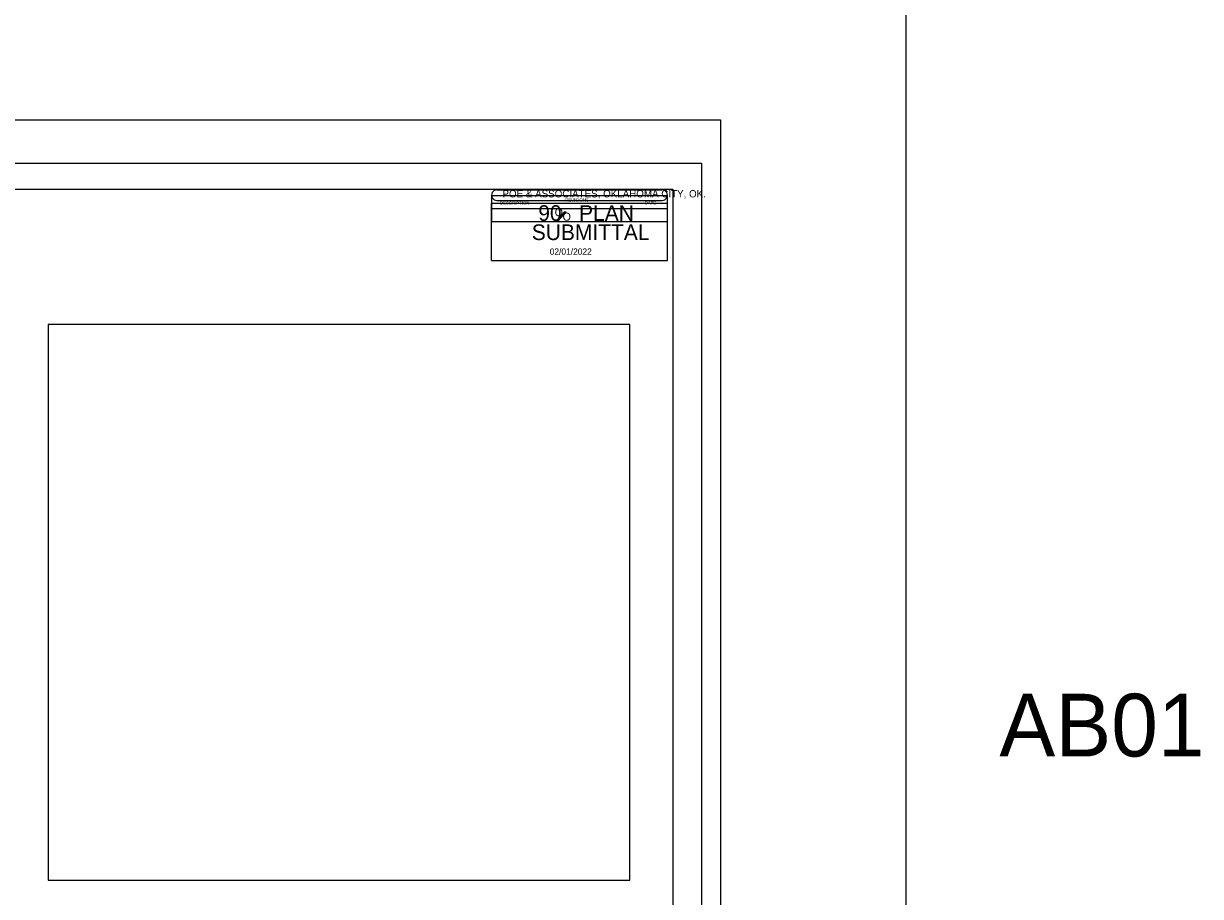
# Model space of a CAD drawing. Extents: x 12306 to 12361.5, y 578.9 to 640.4.
# Drawn here: x 12339.03 to 12361.54, y 593.62 to 610.31 of the extents above; entities that cross this region are included whole.
import ezdxf

# ---------------------------------------------------------------- set-up
doc = ezdxf.new("R2010")
doc.units = 0
for name, color, linetype in [('S', 7, 'Continuous'), ('SHT_Plot_Shape_Full', 7, 'Continuous'), ('SHT_Plot_Shape_Half', 7, 'Continuous'), ('SHT_Sheet_Border', 7, 'Continuous'), ('SHT_Stamp_90_Submit', 7, 'Continuous'), ('SHT_Stamp_Rev_Block', 7, 'Continuous'), ('T', 7, 'Continuous')]:
    doc.layers.add(name, color=color, linetype=linetype)

msp = doc.modelspace()

# ---------------------------------------------------------------- linework, layer by layer
at = {"layer": 'Defpoints'}
msp.add_lwpolyline([(12339.503, 593.929), (12350.628, 593.929), (12350.628, 604.554), (12339.503, 604.554)], close=True, dxfattribs=at)
at = {"layer": 'S'}
msp.add_lwpolyline([(12355.912, 640.357), (12312.476, 640.357), (12312.476, 578.901), (12355.912, 578.901)], close=True, dxfattribs=at)
at = {"layer": 'SHT_Plot_Shape_Full'}
msp.add_lwpolyline([(12316.36, 608.469), (12352.36, 608.469), (12352.36, 584.469), (12316.36, 584.469)], close=True, dxfattribs=at)
at = {"layer": 'SHT_Plot_Shape_Half'}
msp.add_lwpolyline([(12317.998, 607.644), (12351.998, 607.644), (12351.998, 585.644), (12317.998, 585.644)], close=True, dxfattribs=at)
at = {"layer": 'SHT_Sheet_Border'}
msp.add_lwpolyline([(12351.448, 586.144), (12319.948, 586.144), (12319.948, 607.144), (12351.448, 607.144)], close=True, dxfattribs=at)
at = {"layer": 'SHT_Stamp_90_Submit'}
for p, q in [((12348.079, 607.13), (12351.245, 607.13)), ((12347.979, 606.88), (12351.345, 606.88)), ((12347.979, 605.781), (12347.979, 606.88)), ((12348.079, 606.93), (12351.245, 606.93)), ((12351.345, 605.781), (12351.345, 606.88)), ((12349.222, 606.542), (12349.377, 606.714)), ((12349.24, 606.542), (12349.395, 606.714)), ((12349.245, 606.542), (12349.4, 606.714)), ((12349.252, 606.542), (12349.408, 606.714)), ((12349.377, 606.714), (12349.408, 606.714)), ((12349.222, 606.542), (12349.252, 606.542)), ((12347.979, 605.781), (12351.345, 605.781))]:
    msp.add_line(p, q, dxfattribs=at)
for centre, start, end in [((12348.079, 607.03), 89.9952, 270), ((12351.245, 607.03), 270, 90.0048)]:
    msp.add_arc(centre, 0.1, start, end, dxfattribs=at)
at = {"layer": 'SHT_Stamp_Rev_Block'}
for p, q in [((12347.979, 607.02), (12347.979, 606.52)), ((12351.345, 607.02), (12347.979, 607.02)), ((12351.345, 606.52), (12351.345, 607.02)), ((12351.345, 606.77), (12347.979, 606.77)), ((12351.345, 606.52), (12347.979, 606.52))]:
    msp.add_line(p, q, dxfattribs=at)

# ---------------------------------------------------------------- texts
at = {"layer": 'SHT_Stamp_90_Submit'}
for s, height, p in [('POE & ASSOCIATES, OKLAHOMA CITY, OK.', 0.14, (12348.189, 606.987)), ('90   PLAN', 0.3, (12348.874, 606.538)), ('O', 0.153, (12349.187, 606.627)), ('O', 0.153, (12349.339, 606.542)), ('SUBMITTAL', 0.3, (12348.75, 606.171)), ('02/01/2022', 0.12, (12349.093, 605.89))]:
    msp.add_text(s, height=height, rotation=360, dxfattribs=at).set_placement(p)
at = {"layer": 'SHT_Stamp_Rev_Block'}
for s, p in [('DESCRIPTION', (12348.139, 606.849)), ('REVISIONS', (12349.388, 606.908)), ('DATE', (12350.908, 606.853))]:
    msp.add_text(s, height=0.06, dxfattribs=at).set_placement(p)
at = {"layer": 'T'}
msp.add_text('AB01', height=1.2, dxfattribs=at).set_placement((12357.692, 596.293))

doc.saveas('drawing.dxf')
